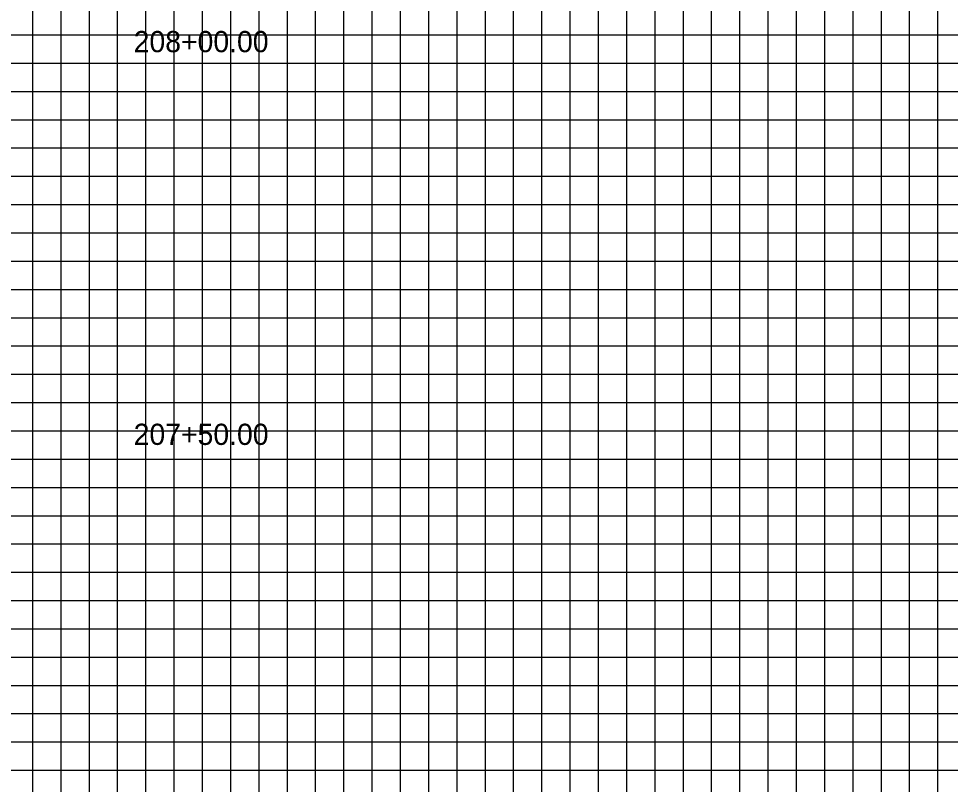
# Model space of a CAD drawing. Extents: x 967 to 1326, y 964 to 1744.
# Drawn here: x 1147 to 1212.9, y 1019 to 1073.1 of the extents above; entities that cross this region are included whole.
import ezdxf

# ---------------------------------------------------------------- set-up
doc = ezdxf.new("R2010")
doc.units = 0
for name, color, linetype in [('Default', 7, 'Continuous'), ('RD_XS_TX_Elev_PR', 7, 'Continuous'), ('RD_XS_TX_Slope', 7, 'Continuous')]:
    doc.layers.add(name, color=color, linetype=linetype)

msp = doc.modelspace()

# ---------------------------------------------------------------- linework, layer by layer
at = {"layer": 'RD_XS_TX_Elev_PR'}
for p, q in [((1150, 1000), (1150, 1170)), ((1160, 1000), (1160, 1170)), ((1170, 1000), (1170, 1170)), ((1180, 1000), (1180, 1170)), ((1190, 1000), (1190, 1170)), ((1200, 1000), (1200, 1170)), ((1210, 1000), (1210, 1170)), ((1000, 1070), (1320, 1070)), ((1000, 1060), (1320, 1060)), ((1000, 1050), (1320, 1050)), ((1000, 1040), (1320, 1040)), ((1000, 1030), (1320, 1030)), ((1000, 1020), (1320, 1020))]:
    msp.add_line(p, q, dxfattribs=at)
at = {"layer": 'RD_XS_TX_Slope'}
for p, q in [((1148, 1000), (1148, 1170)), ((1152, 1000), (1152, 1170)), ((1154, 1000), (1154, 1170)), ((1156, 1000), (1156, 1170)), ((1158, 1000), (1158, 1170)), ((1162, 1000), (1162, 1170)), ((1164, 1000), (1164, 1170)), ((1166, 1000), (1166, 1170)), ((1168, 1000), (1168, 1170)), ((1172, 1000), (1172, 1170)), ((1174, 1000), (1174, 1170)), ((1176, 1000), (1176, 1170)), ((1178, 1000), (1178, 1170)), ((1182, 1000), (1182, 1170)), ((1184, 1000), (1184, 1170)), ((1186, 1000), (1186, 1170)), ((1188, 1000), (1188, 1170)), ((1192, 1000), (1192, 1170)), ((1194, 1000), (1194, 1170)), ((1196, 1000), (1196, 1170)), ((1198, 1000), (1198, 1170)), ((1202, 1000), (1202, 1170)), ((1204, 1000), (1204, 1170)), ((1206, 1000), (1206, 1170)), ((1208, 1000), (1208, 1170)), ((1212, 1000), (1212, 1170)), ((1000, 1072), (1320, 1072)), ((1000, 1068), (1320, 1068)), ((1000, 1066), (1320, 1066)), ((1000, 1064), (1320, 1064)), ((1000, 1062), (1320, 1062)), ((1000, 1058), (1320, 1058)), ((1000, 1056), (1320, 1056)), ((1000, 1054), (1320, 1054)), ((1000, 1052), (1320, 1052)), ((1000, 1048), (1320, 1048)), ((1000, 1046), (1320, 1046)), ((1000, 1044), (1320, 1044)), ((1000, 1042), (1320, 1042)), ((1000, 1038), (1320, 1038)), ((1000, 1036), (1320, 1036)), ((1000, 1034), (1320, 1034)), ((1000, 1032), (1320, 1032)), ((1000, 1028), (1320, 1028)), ((1000, 1026), (1320, 1026)), ((1000, 1024), (1320, 1024)), ((1000, 1022), (1320, 1022))]:
    msp.add_line(p, q, dxfattribs=at)

# ---------------------------------------------------------------- texts
at = {"layer": 'Default'}
for s, p in [('208+00.00', (1155.134, 1070.774)), ('207+50.00', (1155.134, 1043.004))]:
    msp.add_text(s, height=1.5, dxfattribs=at).set_placement(p)

doc.saveas('drawing.dxf')
